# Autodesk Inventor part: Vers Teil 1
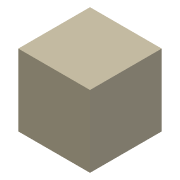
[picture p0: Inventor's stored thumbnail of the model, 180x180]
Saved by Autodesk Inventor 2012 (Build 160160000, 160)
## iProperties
Created: 2004-10
Part Number: Vers Teil 1
Document SubType Name: Modeling
Designer: jukr
Manufacturer: Standard
Standards Organization: Custom
Density: 1 g/cm^3
Material: Standard
Author: jukr
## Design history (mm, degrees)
sketch "Skizze1"
  geometry: L1 (-37.452, 13.181)-(12.548, 13.181); L2 (12.548, 13.181)-(12.548, -36.819); L3 (12.548, -36.819)-(-37.452, -36.819); L4 (-37.452, -36.819)-(-37.452, 13.181)
  constraints: 8 end point, 2 parallel, 1 horizontal, 1 perpendicular
  dimensions: "d0" = 50 distance of L1.start L1.end (= d1); "d1" = 50 distance of L3.end L1.start
extrude "Extrusion1" new body sketch "Skizze1" distance "d2" = 50; taper "d3" = 0 deg
node "Volumenkörper1"
node "Volumenkörpern"
node "Oberflächenkörpern"
